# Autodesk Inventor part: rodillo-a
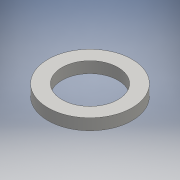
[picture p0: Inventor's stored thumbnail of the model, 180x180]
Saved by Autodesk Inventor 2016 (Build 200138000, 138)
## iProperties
Created: 2016-06
Part Number: rodillo-a
Material: Genérico
Document SubType Name: Modeling
Designer: adm
Density: 1 g/cm^3
Appearance: Valor por defecto
Author: adm
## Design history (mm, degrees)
sketch "Boceto1"
  geometry: C1 r 10 at (0, 0); C2 r 15 at (0, 0); 1 further point
  constraints: 2 centre point, 1 coincident
  dimensions: "d0" = 20 diameter of C1; "d1" = 5 radial gap between concentric circles of C1 C2
extrude "Extrusión1" new body sketch "Boceto1" distance "d2" = 4; taper "d3" = 0 deg
node "Sólido1"
